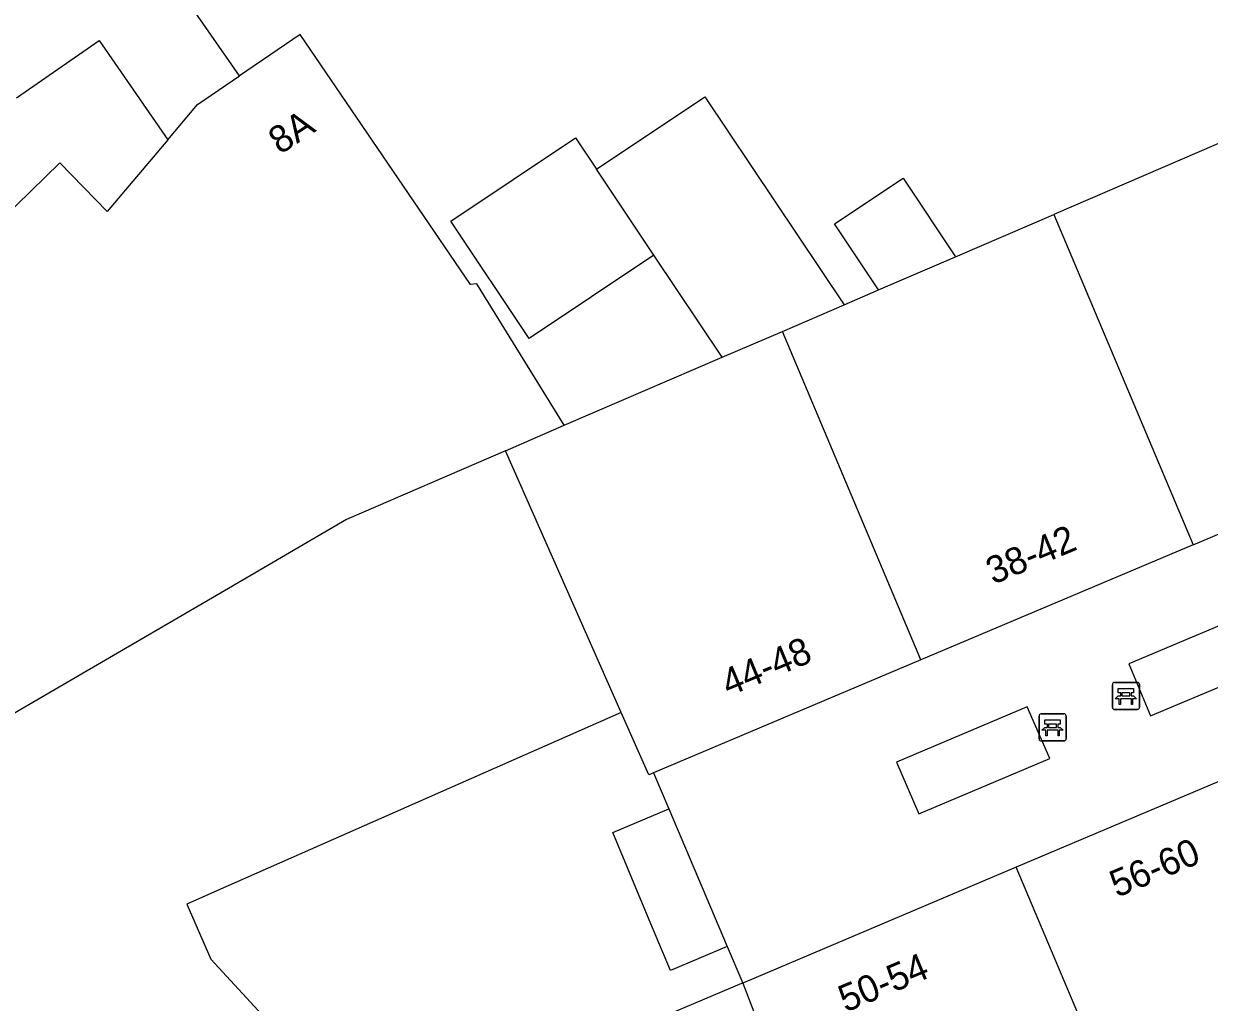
# Model space of a CAD drawing. Extents: x 161771 to 163125, y 382479 to 383177.
# Drawn here: x 161851 to 161894.8, y 382984.8 to 383020.94 of the extents above; entities that cross this region are included whole.
import ezdxf

# ---------------------------------------------------------------- set-up
doc = ezdxf.new("R2010")
doc.units = 0
for name, color, linetype in [('IMGEO_Bank', 7, 'Continuous'), ('IMGEO_Pand', 7, 'Continuous'), ('IMGEO_Pand_nummerreeks', 7, 'Continuous'), ('IMGEO_Voetpad_open', 7, 'Continuous')]:
    doc.layers.add(name, color=color, linetype=linetype)

msp = doc.modelspace()

# ---------------------------------------------------------------- linework, layer by layer
at = {"layer": 'IMGEO_Bank'}
for p, q in [((161891.216, 382995.689), (161891.216, 382996.53)), ((161891.216, 382996.53), (161891.216, 382995.689)), ((161891.291, 382996.614), (161892.132, 382996.614)), ((161892.132, 382996.614), (161891.291, 382996.614)), ((161892.216, 382996.539), (161892.216, 382995.698)), ((161892.216, 382995.698), (161892.216, 382996.539)), ((161891.913, 382996.012), (161891.52, 382996.012)), ((161891.525, 382996.12), (161891.525, 382996.226)), ((161891.569, 382996.226), (161891.569, 382996.12)), ((161891.857, 382996.232), (161891.575, 382996.232)), ((161891.575, 382996.114), (161891.857, 382996.114)), ((161891.863, 382996.12), (161891.863, 382996.226)), ((161891.907, 382996.226), (161891.907, 382996.12)), ((161888.582, 382995.453), (161889.423, 382995.453)), ((161889.423, 382995.453), (161888.582, 382995.453)), ((161889.507, 382995.378), (161889.507, 382994.537)), ((161889.507, 382994.537), (161889.507, 382995.378)), ((161892.141, 382995.614), (161891.3, 382995.614)), ((161891.3, 382995.614), (161892.141, 382995.614)), ((161888.507, 382994.528), (161888.507, 382995.369)), ((161888.507, 382995.369), (161888.507, 382994.528)), ((161888.816, 382994.959), (161888.816, 382995.065)), ((161888.86, 382995.065), (161888.86, 382994.959)), ((161889.148, 382995.071), (161888.866, 382995.071)), ((161888.866, 382994.953), (161889.148, 382994.953)), ((161889.154, 382994.959), (161889.154, 382995.065)), ((161889.198, 382995.065), (161889.198, 382994.959)), ((161889.204, 382994.851), (161888.811, 382994.851)), ((161889.432, 382994.453), (161888.591, 382994.453)), ((161888.591, 382994.453), (161889.432, 382994.453))]:
    msp.add_line(p, q, dxfattribs=at)
for points in [[(161891.519, 382996.232), (161891.433, 382996.232), (161891.433, 382996.393), (161891.996, 382996.393), (161891.996, 382996.232), (161891.913, 382996.232)], [(161891.463, 382996.012), (161891.321, 382996.012), (161891.433, 382996.114), (161891.519, 382996.114)], [(161891.513, 382996.005), (161891.513, 382995.798), (161891.47, 382995.798), (161891.47, 382996.005)], [(161891.913, 382996.114), (161891.996, 382996.114), (161892.108, 382996.012), (161891.969, 382996.012)], [(161891.963, 382996.005), (161891.963, 382995.798), (161891.919, 382995.798), (161891.919, 382996.005)], [(161888.754, 382994.851), (161888.612, 382994.851), (161888.724, 382994.953), (161888.81, 382994.953)], [(161888.81, 382995.071), (161888.724, 382995.071), (161888.724, 382995.232), (161889.287, 382995.232), (161889.287, 382995.071), (161889.204, 382995.071)], [(161889.204, 382994.953), (161889.287, 382994.953), (161889.399, 382994.851), (161889.26, 382994.851)], [(161888.804, 382994.844), (161888.804, 382994.637), (161888.761, 382994.637), (161888.761, 382994.844)], [(161889.254, 382994.844), (161889.254, 382994.637), (161889.21, 382994.637), (161889.21, 382994.844)]]:
    msp.add_lwpolyline(points, dxfattribs=at)
for centre, radius, start, end in [((161891.294, 382996.536), 0.0779, 92.4484, 184.2845), ((161891.294, 382996.536), 0.0779, 92.4484, 184.2845), ((161892.138, 382996.536), 0.0779, 2.4484, 94.2845), ((161892.138, 382996.536), 0.0779, 2.4484, 94.2845), ((161891.463, 382996.005), 0.00671, 2.8957, 87.1043), ((161891.52, 382996.005), 0.00671, 92.8957, 177.1043), ((161891.518, 382996.225), 0.00671, 2.8957, 87.1043), ((161891.518, 382996.121), 0.00671, 272.8957, 357.1043), ((161891.575, 382996.225), 0.00671, 92.8957, 177.1043), ((161891.575, 382996.121), 0.00671, 182.8957, 267.1043), ((161891.857, 382996.225), 0.00671, 2.8957, 87.1043), ((161891.857, 382996.121), 0.00671, 272.8957, 357.1043), ((161891.914, 382996.225), 0.00671, 92.8957, 177.1043), ((161891.914, 382996.121), 0.00671, 182.8957, 267.1043), ((161891.912, 382996.005), 0.00671, 2.8957, 87.1043), ((161891.969, 382996.005), 0.00671, 92.8957, 177.1043), ((161888.585, 382995.375), 0.0779, 92.4484, 184.2845), ((161888.585, 382995.375), 0.0779, 92.4484, 184.2845), ((161889.429, 382995.375), 0.0779, 2.4484, 94.2845), ((161889.429, 382995.375), 0.0779, 2.4484, 94.2845), ((161891.294, 382995.692), 0.0779, 182.4484, 274.2845), ((161891.294, 382995.692), 0.0779, 182.4484, 274.2845), ((161892.138, 382995.692), 0.0779, 272.4484, 4.2845), ((161892.138, 382995.692), 0.0779, 272.4484, 4.2845), ((161888.809, 382995.064), 0.00671, 2.8957, 87.1043), ((161888.809, 382994.96), 0.00671, 272.8957, 357.1043), ((161888.866, 382995.064), 0.00671, 92.8957, 177.1043), ((161888.866, 382994.96), 0.00671, 182.8957, 267.1043), ((161889.148, 382995.064), 0.00671, 2.8957, 87.1043), ((161889.148, 382994.96), 0.00671, 272.8957, 357.1043), ((161889.205, 382995.064), 0.00671, 92.8957, 177.1043), ((161889.205, 382994.96), 0.00671, 182.8957, 267.1043), ((161888.585, 382994.531), 0.0779, 182.4484, 274.2845), ((161888.585, 382994.531), 0.0779, 182.4484, 274.2845), ((161888.754, 382994.844), 0.00671, 2.8957, 87.1043), ((161888.811, 382994.844), 0.00671, 92.8957, 177.1043), ((161889.203, 382994.844), 0.00671, 2.8957, 87.1043), ((161889.26, 382994.844), 0.00671, 92.8957, 177.1043), ((161889.429, 382994.531), 0.0779, 272.4484, 4.2845), ((161889.429, 382994.531), 0.0779, 272.4484, 4.2845)]:
    msp.add_arc(centre, radius, start, end, dxfattribs=at)
at = {"layer": 'IMGEO_Pand'}
for points in [[(161858.967, 383019.01), (161856.682, 383022.319), (161854.66, 383025.247), (161851.818, 383029.361)], [(161870.967, 383006.109), (161867.739, 383011.331), (161867.5, 383011.314), (161861.215, 383020.541), (161858.967, 383019.01)], [(161850.725, 383018.205), (161853.785, 383020.318), (161856.318, 383016.651)], [(161856.318, 383016.651), (161857.42, 383017.957), (161858.967, 383019.01)], [(161872.157, 383015.565), (161876.164, 383018.244), (161881.301, 383010.558)], [(161899.078, 383018.211), (161889.05, 383013.894)], [(161856.318, 383016.651), (161854.084, 383014.004), (161852.334, 383015.802), (161846.999, 383010.61), (161847.856, 383009.731), (161846.846, 383008.361), (161846.6, 383008.389), (161842.149, 383002.352), (161841.261, 383003.516), (161839.941, 383002.509), (161839.747, 383002.763), (161839.342, 383002.454), (161837.414, 383000.982), (161836.127, 383000), (161833.959, 382998.347)], [(161874.278, 383012.391), (161869.668, 383009.31), (161866.77, 383013.645), (161871.38, 383016.727), (161872.157, 383015.565)], [(161874.278, 383012.391), (161872.157, 383015.565)], [(161882.579, 383011.108), (161880.951, 383013.544), (161883.484, 383015.237), (161885.425, 383012.333)], [(161885.425, 383012.333), (161889.05, 383013.894)], [(161889.05, 383013.894), (161894.202, 383001.701)], [(161876.799, 383008.62), (161874.278, 383012.391)], [(161882.579, 383011.108), (161885.425, 383012.333)], [(161881.301, 383010.558), (161882.579, 383011.108)], [(161879.023, 383009.577), (161881.301, 383010.558)], [(161876.799, 383008.62), (161879.023, 383009.577)], [(161884.145, 382997.452), (161879.023, 383009.577)], [(161870.967, 383006.109), (161876.799, 383008.62)], [(161868.791, 383005.167), (161870.967, 383006.109)], [(161894.202, 383001.701), (161904.258, 383005.95)], [(161868.791, 383005.167), (161862.923, 383002.628), (161858.411, 383000), (161849.9, 382995.042), (161842.917, 382985.687), (161842.777, 382985.497)], [(161873.071, 382995.502), (161868.791, 383005.167)], [(161894.202, 383001.701), (161884.145, 382997.452)], [(161884.145, 382997.452), (161874.263, 382993.277)], [(161873.071, 382995.502), (161858.047, 382988.879), (161857.021, 382988.427), (161857.914, 382986.399), (161861.704, 382982.283), (161861.155, 382981.758), (161860.975, 382981.946), (161854.902, 382976.268), (161855.08, 382976.079), (161853.388, 382974.49)], [(161874.263, 382993.277), (161874.09, 382993.201), (161873.071, 382995.502)], [(161897.768, 382994.06), (161887.664, 382989.786)], [(161887.664, 382989.786), (161877.561, 382985.513)], [(161893.122, 382976.882), (161887.664, 382989.786)], [(161855.115, 382972.647), (161856.806, 382974.236), (161856.984, 382974.046), (161863.139, 382979.842), (161862.959, 382980.03), (161863.429, 382980.479), (161864.072, 382979.807), (161877.532, 382985.501), (161877.561, 382985.513)], [(161877.561, 382985.513), (161879.855, 382979.541), (161879.099, 382979.173)]]:
    msp.add_lwpolyline(points, dxfattribs=at)
at = {"layer": 'IMGEO_Voetpad_open'}
for points in [[(161891.818, 382997.298), (161892.619, 382995.378), (161897.606, 382997.472), (161896.795, 382999.388), (161891.818, 382997.298)], [(161883.245, 382993.665), (161884.06, 382991.762), (161888.904, 382993.801), (161888.068, 382995.707), (161883.245, 382993.665)], [(161874.263, 382993.277), (161874.828, 382991.943)], [(161876.983, 382986.857), (161874.887, 382985.971), (161874.164, 382987.699), (161872.76, 382991.07), (161874.828, 382991.943)], [(161874.828, 382991.943), (161876.983, 382986.857)], [(161876.983, 382986.857), (161877.561, 382985.513)]]:
    msp.add_lwpolyline(points, dxfattribs=at)

# ---------------------------------------------------------------- texts
at = {"layer": 'IMGEO_Pand_nummerreeks'}
for s, rotation, p in [('8A', 33.2659, (161860.467, 383016.09)), ('38-42', 22.7063, (161886.815, 383000.217)), ('44-48', 22.7063, (161877.038, 382996.086)), ('56-60', 22.7292, (161891.386, 382988.655)), ('50-54', 22.7292, (161881.361, 382984.415))]:
    msp.add_text(s, height=1, rotation=rotation, dxfattribs=at).set_placement(p)

doc.saveas('drawing.dxf')
